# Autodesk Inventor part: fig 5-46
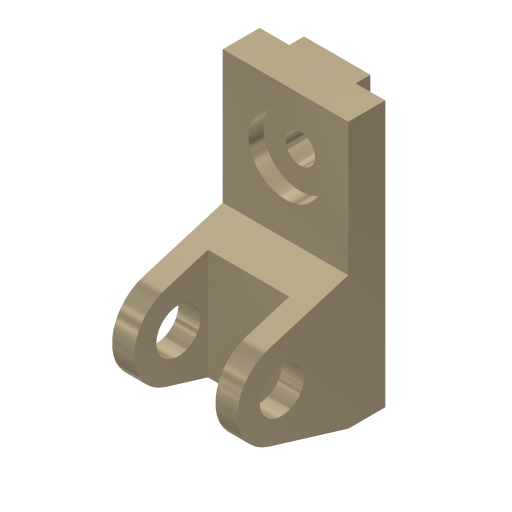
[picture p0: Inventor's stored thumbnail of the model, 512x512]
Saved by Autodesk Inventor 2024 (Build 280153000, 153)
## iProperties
Shininess: 65.0
Angle Display Precision: 2
Document Length Units: 11269
Document Angle Units: 11279
Document Time Units: 11290
Document Mass Units: 11283
Document Length Units Precision: 3
Document Angle Units Precision: 2
Created: 2001-11
Part Number: fig 5-46
Document SubType Name: Modeling
Designer: Renu Muthoo
Density: 1 g/cm^3
Material: Generic
Appearance: Metal-Titanium (Polished)
Density: 0.0
Volumn: 0.0
Area: 0.0
PropertySet Name: Model Information
Control State: 0
Master: False
Checked Out: False
Author: Renu Muthoo
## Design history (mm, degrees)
sketch "Sketch2"
  geometry: L1 (33.257, 104.664)-(33.257, -75.336); L2 (33.257, -75.336)-(8.257, -75.336); L3 (8.257, -75.336)-(-45.451, -59.045); L4 (-45.451, -1.628)-(8.257, 14.664); L5 (8.257, 14.664)-(8.257, 104.664); L6 (8.257, 104.664)-(33.257, 104.664); C1 r 15 at (-36.743, -30.336); A1 r 30 centre (-36.743, -30.336) between (-45.451, -1.628) and (-45.451, -59.045)
  constraints: 12 end point, 2 centre point, 2 equal length, 2 parallel, 2 point on circle, 2 tangent, 1 coincident, 1 perpendicular, 1 vertical
  dimensions: "d0" = 180 distance of L1.start L1.end; "d1" = 30 radius of A1; "d2" = 25 distance of L5.end L1.start; "d3" = 45 distance from line of L2 A1.centre; "d4" = 70 distance from line of L1 A1.centre; "d5" = 30 diameter of C1
extrude "Extrusion1" new body sketch "Sketch2" distance "d6" = 85; taper "d7" = 0 deg
workplane "Work Plane1"
sketch "Sketch3"
  geometry: L1 (15, 62.364)-(70, 62.364); L2 (70, 62.364)-(70, -52.386); L3 (70, -52.386)-(15, -52.386); L4 (15, -52.386)-(15, 62.364); L5 (0, -45)-(0, -28.708) reference
  constraints: 8 end point, 2 parallel, 1 horizontal, 1 perpendicular
  dimensions: "d8" = 55 distance of L1.start L1.end; "d9" = 15 distance between parallel lines of L5 L4
extrude "Extrusion2" cut sketch "Sketch3" distance "d10" = 50; taper "d11" = 0 deg
sketch "Sketch4"
  geometry: L1 (0, 25)-(85, 25) reference; L2 (0, 0)-(0, 25) reference; L3 (20, 25)-(65, 25); L4 (65, 25)-(65, 35); L5 (65, 35)-(20, 35); L6 (20, 35)-(20, 25)
  constraints: 8 end point, 2 parallel, 1 horizontal, 1 perpendicular, 1 point on line
  dimensions: "d12" = 45 distance of L4.end L5.end; "d13" = 10 distance of L3.end L4.end; "d14" = 20 distance between parallel lines of L2 L6
extrude "Extrusion3" join sketch "Sketch4" stored distance "d15" = 50; taper "d16" = 0 deg
sketch "Sketch5"
  geometry: L1 (85, 0)-(85, 90) reference; L2 (0, 90)-(85, 90) reference; 1 further point
  dimensions: "d17" = 42 distance from line of L2 point (42.5, 48); "d18" = 42.5 distance from line of L1 point (42.5, 48)
hole "Hole1" sketch "Sketch5" diameter "d19" = 20; stored, may be unused: countersink angle "d23" = 82 deg, drill point angle "d25" = 118 deg; dims "d20" = 6, "d21" = 50, "d22" = 10, "d24" = 8
workpoint "Work Point5"
body "Solid1"
node "Sketch1"
